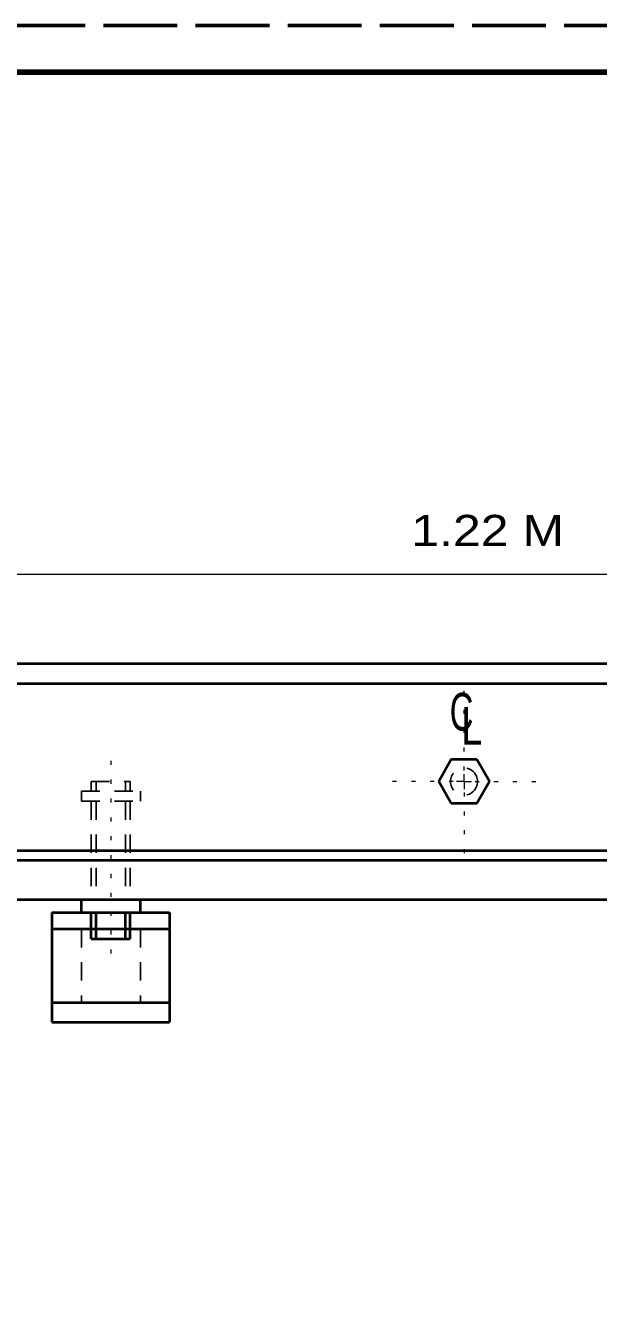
# Model space of a CAD drawing. Extents: x 312583 to 312853, y 144419 to 144586.
# Drawn here: x 312733.29 to 312747.29, y 144555.29 to 144586.22 of the extents above; entities that cross this region are included whole.
import ezdxf

# ---------------------------------------------------------------- set-up
doc = ezdxf.new("R2010")
doc.units = 0
doc.header["$LTSCALE"] = 0.3
for name, pattern in [('DOTTED', [1.5, 0.3, -1.2]), ('LONG_DASHED', [7.5, 6, -1.5]), ('SHORT_DASHED', [2.7, 1.5, -1.2])]:
    doc.linetypes.add(name, pattern=pattern)
doc.layers.add('1', color=7, linetype='Continuous', lineweight=40)
doc.layers.add('2', color=7, linetype='Continuous', lineweight=13)

msp = doc.modelspace()

# ---------------------------------------------------------------- linework, layer by layer
at = {"layer": '1', "linetype": 'LONG_DASHED', "lineweight": 60}
msp.add_line((312851.75, 144586.2246), (312583.526, 144586.2246), dxfattribs=at)
msp.add_line((312851.75, 144586.2246), (312583.526, 144586.2246), dxfattribs=at)
at = {"layer": '1'}
for p, q in [((312721.0054, 144570.6589), (312767.0054, 144570.6589)), ((312744.6264, 144567.7839), (312744.312, 144568.3206)), ((312743.691, 144567.2472), (312743.3844, 144567.7839)), ((312744.6264, 144567.7839), (312744.312, 144567.2472)), ((312744.312, 144567.2472), (312743.691, 144567.2472)), ((312726.7554, 144564.9089), (312747.9307, 144564.9089)), ((312734.6597, 144564.5869), (312734.6597, 144564.9089)), ((312736.101, 144564.5869), (312736.101, 144564.9089)), ((312733.939, 144564.5869), (312733.939, 144561.9112)), ((312733.939, 144564.5869), (312736.814, 144564.5869)), ((312734.8974, 144563.9506), (312734.8974, 144564.5869)), ((312735.02, 144563.9506), (312735.02, 144564.5869)), ((312735.7407, 144563.9506), (312735.7407, 144564.5869)), ((312735.8557, 144563.9506), (312735.8557, 144564.5869)), ((312736.814, 144564.5869), (312736.814, 144561.9112)), ((312733.939, 144564.1882), (312736.814, 144564.1882)), ((312734.8974, 144563.9506), (312735.8557, 144563.9506)), ((312733.939, 144562.3942), (312736.814, 144562.3942)), ((312733.939, 144561.9112), (312736.814, 144561.9112))]:
    msp.add_line(p, q, dxfattribs=at)
at = {"layer": '1', "linetype": 'DOTTED', "lineweight": 13}
msp.add_line((312735.3804, 144568.2899), (312735.3804, 144563.4676), dxfattribs=at)
at = {"layer": '1', "linetype": 'SHORT_DASHED', "lineweight": 25}
for p, q in [((312734.8974, 144567.7839), (312735.8557, 144567.7839)), ((312734.8974, 144567.7839), (312734.8974, 144567.5462)), ((312735.02, 144567.7839), (312735.02, 144567.5462)), ((312735.7407, 144567.7839), (312735.7407, 144567.5462)), ((312735.8557, 144567.7839), (312735.8557, 144567.5462)), ((312734.6597, 144567.5462), (312736.101, 144567.5462)), ((312734.6597, 144567.5462), (312734.6597, 144567.3009)), ((312736.101, 144567.5462), (312736.101, 144567.3009)), ((312734.6597, 144567.3009), (312736.101, 144567.3009)), ((312734.8974, 144567.3009), (312734.8974, 144564.9089)), ((312735.02, 144567.3009), (312735.02, 144564.9089)), ((312735.7407, 144567.3009), (312735.7407, 144564.9089)), ((312735.8557, 144567.3009), (312735.8557, 144564.9089)), ((312734.6597, 144564.1882), (312734.6597, 144562.3942)), ((312736.101, 144564.1882), (312736.101, 144562.3942))]:
    msp.add_line(p, q, dxfattribs=at)
at = {"layer": '1', "lineweight": 158}
msp.add_lwpolyline([(312616.5, 144423.1446), (312616.5, 144585.0846), (312849, 144585.0846)], dxfattribs=at)
at = {"layer": '1'}
for points in [[(312721.4807, 144570.1759), (312766.5224, 144570.1759), (312766.5224, 144542.3842)], [(312744.312, 144568.3206), (312743.691, 144568.3206), (312743.3844, 144567.7839)], [(312725.5594, 144566.1049), (312762.4514, 144566.1049), (312762.4514, 144546.4629)], [(312725.797, 144565.8672), (312762.2137, 144565.8672), (312762.2137, 144546.7006)]]:
    msp.add_lwpolyline(points, dxfattribs=at)
at = {"layer": '1', "linetype": 'SHORT_DASHED', "lineweight": 25}
msp.add_circle((312744.0035, 144567.7829), 0.3301, dxfattribs=at)
at = {"layer": '2'}
for p, q in [((312721.0054, 144572.8439), (312767.0054, 144572.8439)), ((312744.0054, 144567.7839), (312743.8214, 144567.7839)), ((312744.0054, 144567.7839), (312744.0054, 144567.9602)), ((312744.0054, 144567.7839), (312744.0054, 144567.5999)), ((312744.0054, 144567.7839), (312744.1817, 144567.7839))]:
    msp.add_line(p, q, dxfattribs=at)
at = {"layer": '2', "linetype": 'DOTTED'}
for p, q in [((312744.0054, 144568.0522), (312744.0054, 144570.2296)), ((312743.737, 144567.7839), (312741.9354, 144567.7839)), ((312744.2737, 144567.7839), (312746.0677, 144567.7839)), ((312744.0054, 144567.5156), (312744.0054, 144565.7139))]:
    msp.add_line(p, q, dxfattribs=at)

# ---------------------------------------------------------------- texts
at = {"layer": '2'}
for s, height, width, p in [('1.22 M', 0.76, 1.2, (312742.715, 144573.5262)), ('C', 0.92, 0.65, (312743.6527, 144569.0259)), ('L', 0.92, 0.75, (312743.9364, 144568.6809))]:
    msp.add_text(s, height=height, dxfattribs=dict(at, width=width)).set_placement(p)

doc.saveas('drawing.dxf')
